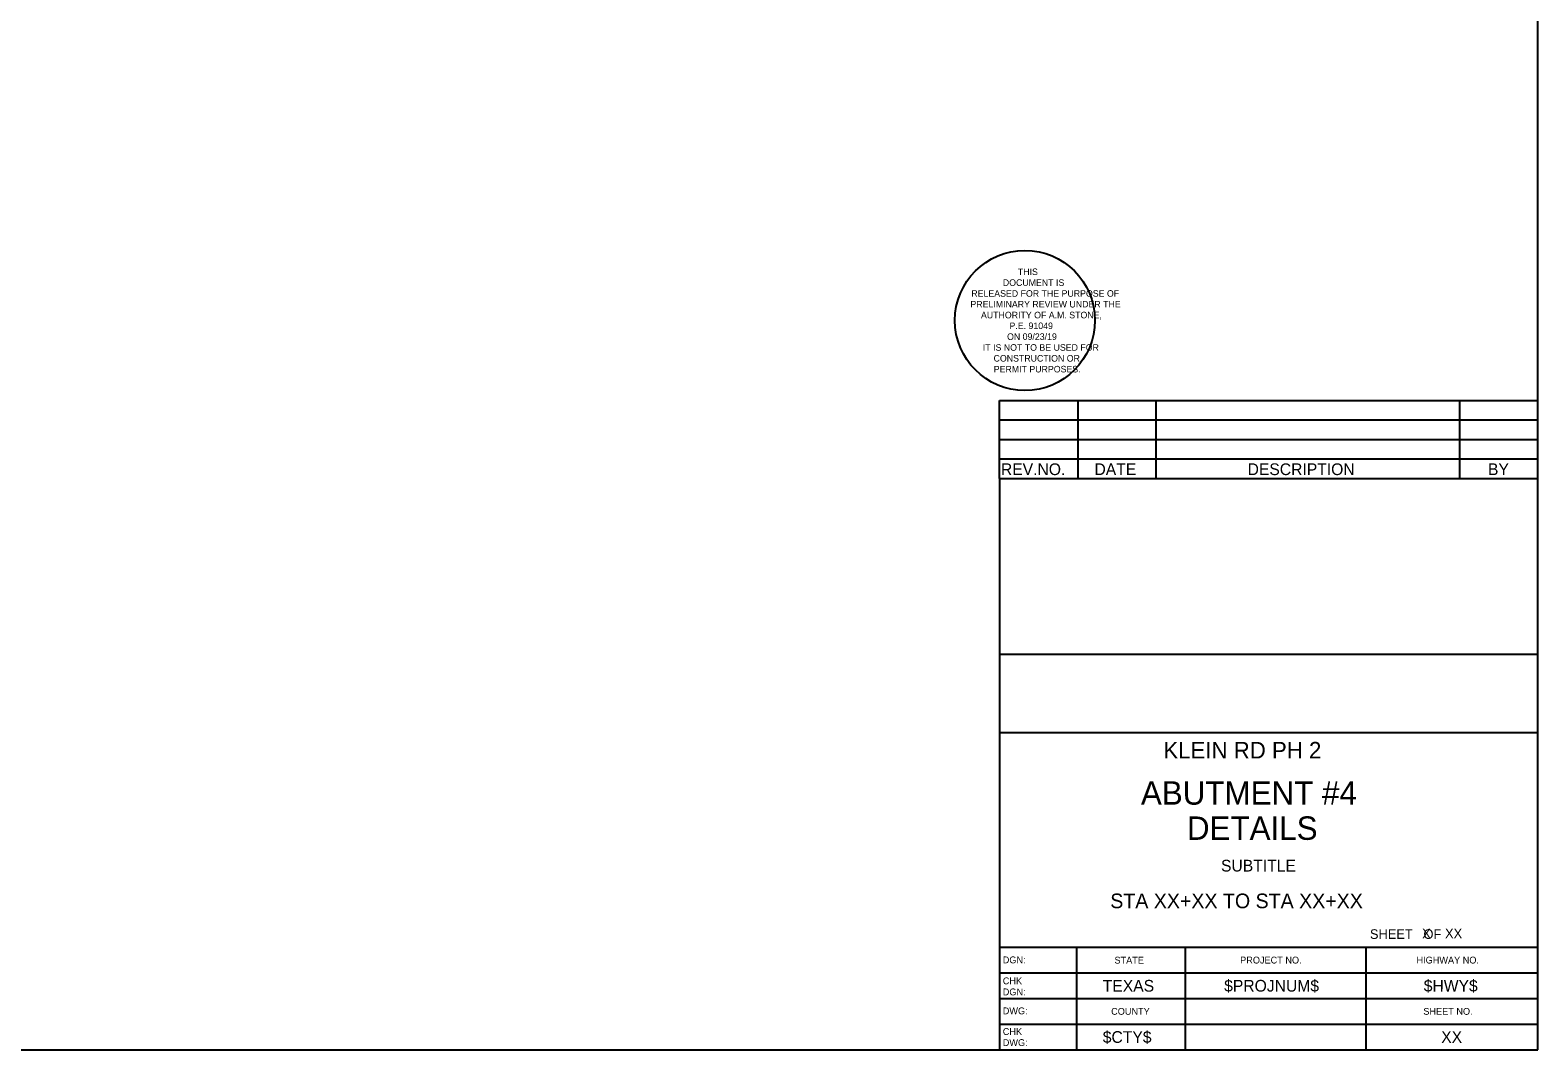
# Model space of a CAD drawing. Extents: x 926 to 1074, y 990 to 1081.
# Drawn here: x 1052.32 to 1067.76, y 1024.24 to 1034.69 of the extents above; entities that cross this region are included whole.
import ezdxf

# ---------------------------------------------------------------- set-up
doc = ezdxf.new("R2010")
doc.units = 0
for name, color, linetype in [('BORD_lines_major', 7, 'Continuous'), ('BORD_lines_minor', 7, 'Continuous'), ('BORD_text_large_1', 7, 'Continuous'), ('BORD_text_large_2', 7, 'Continuous'), ('BORD_text_SHEET', 7, 'Continuous'), ('BORD_text_small_1', 7, 'Continuous'), ('BORD_text_small_2', 7, 'Continuous'), ('BORD_text_small_3', 7, 'Continuous'), ('BORD_text_small_proj', 7, 'Continuous'), ('C-MS-ANNO-TTLB-STMP', 7, 'Continuous')]:
    doc.layers.add(name, color=color, linetype=linetype)

msp = doc.modelspace()

# ---------------------------------------------------------------- linework, layer by layer
at = {"layer": 'BORD_lines_major'}
for p, q in [((1067.759, 1024.245), (1067.759, 1045.127)), ((1036.673, 1024.245), (1067.759, 1024.245))]:
    msp.add_line(p, q, dxfattribs=at)
at = {"layer": 'BORD_lines_minor'}
for p, q in [((1062.248, 1030.895), (1067.759, 1030.895)), ((1062.248, 1030.095), (1062.248, 1030.895)), ((1063.048, 1030.895), (1063.048, 1030.095)), ((1063.848, 1030.895), (1063.848, 1030.095)), ((1066.959, 1030.095), (1066.959, 1030.895)), ((1062.248, 1030.695), (1067.759, 1030.695)), ((1062.248, 1030.495), (1067.759, 1030.495)), ((1062.248, 1030.295), (1067.759, 1030.295)), ((1062.248, 1030.095), (1067.759, 1030.095)), ((1062.248, 1030.095), (1062.248, 1028.295)), ((1062.248, 1028.295), (1067.759, 1028.295)), ((1062.248, 1028.295), (1062.248, 1024.245)), ((1062.248, 1027.495), (1067.759, 1027.495)), ((1062.248, 1025.295), (1067.759, 1025.295)), ((1063.035, 1025.295), (1063.035, 1024.245)), ((1064.148, 1025.295), (1064.148, 1024.245)), ((1065.998, 1025.295), (1065.998, 1024.245)), ((1062.248, 1025.032), (1067.759, 1025.032)), ((1062.248, 1024.77), (1067.759, 1024.77)), ((1062.248, 1024.507), (1067.759, 1024.507))]:
    msp.add_line(p, q, dxfattribs=at)
at = {"layer": 'C-MS-ANNO-TTLB-STMP'}
msp.add_circle((1062.507, 1031.713), 0.717, dxfattribs=at)

# ---------------------------------------------------------------- texts
at = {"layer": 'BORD_lines_minor'}
for s, p in [('REV.NO.', (1062.261, 1030.13)), ('DATE', (1063.219, 1030.13)), ('DESCRIPTION', (1064.787, 1030.13)), ('BY', (1067.249, 1030.13))]:
    msp.add_text(s, height=0.12, rotation=359.9834, dxfattribs=at).set_placement(p)
msp.add_text('KLEIN RD PH 2', height=0.17, dxfattribs=at).set_placement((1063.925, 1027.228))
at = {"layer": 'BORD_text_large_1'}
for s, p in [('ABUTMENT #4', (1063.695, 1026.755)), ('DETAILS', (1064.166, 1026.395))]:
    msp.add_text(s, height=0.24, dxfattribs=at).set_placement(p)
at = {"layer": 'BORD_text_large_2'}
msp.add_text('STA XX+XX TO STA XX+XX', height=0.15, dxfattribs=at).set_placement((1063.381, 1025.695))
at = {"layer": 'BORD_text_SHEET'}
msp.add_text('XX', height=0.12, dxfattribs=at).set_placement((1066.77, 1024.316))
at = {"layer": 'BORD_text_small_1'}
msp.add_text('SHEET   OF', height=0.0984, dxfattribs=at).set_placement((1066.04, 1025.381))
at = {"layer": 'BORD_text_small_2'}
msp.add_text('SUBTITLE', height=0.12, rotation=359.9834, dxfattribs=at).set_placement((1064.515, 1026.071))
at = {"layer": 'BORD_text_small_3'}
msp.add_text('X    XX', height=0.0984, dxfattribs=at).set_placement((1066.575, 1025.387))
at = {"layer": 'BORD_text_small_proj'}
for s, height, p in [('DGN:', 0.07, (1062.28, 1025.131)), ('STATE', 0.07, (1063.424, 1025.128)), ('PROJECT NO.', 0.07, (1064.711, 1025.129)), ('HIGHWAY NO.', 0.07, (1066.517, 1025.129)), ('CHK', 0.07, (1062.28, 1024.916)), ('DGN:', 0.07, (1062.28, 1024.803)), ('TEXAS', 0.12, (1063.304, 1024.841)), ('$HWY$', 0.12, (1066.591, 1024.841)), ('DWG:', 0.07, (1062.28, 1024.609)), ('COUNTY', 0.07, (1063.39, 1024.604)), ('SHEET NO.', 0.07, (1066.587, 1024.604)), ('CHK', 0.07, (1062.28, 1024.397)), ('$CTY$', 0.12, (1063.304, 1024.316)), ('DWG:', 0.07, (1062.28, 1024.284))]:
    msp.add_text(s, height=height, rotation=359.9834, dxfattribs=at).set_placement(p)
msp.add_text('$PROJNUM$', height=0.12, dxfattribs=at).set_placement((1064.547, 1024.841))
at = {"layer": 'C-MS-ANNO-TTLB-STMP'}
for s, height, p in [('DOCUMENT IS', 0.06723, (1062.281, 1032.067)), ('THIS', 0.0672, (1062.435, 1032.178)), ('RELEASED FOR THE PURPOSE OF', 0.06723, (1061.958, 1031.956)), ('PRELIMINARY REVIEW UNDER THE', 0.06723, (1061.949, 1031.846)), ('AUTHORITY OF A.M. STONE,', 0.06723, (1062.057, 1031.735)), ('P.E. 91049', 0.0672, (1062.349, 1031.625)), ('ON 09/23/19', 0.06723, (1062.324, 1031.514)), ('IT IS NOT TO BE USED FOR', 0.06723, (1062.076, 1031.403)), ('CONSTRUCTION OR', 0.06723, (1062.186, 1031.292)), ('PERMIT PURPOSES.', 0.06723, (1062.188, 1031.181))]:
    msp.add_text(s, height=height, rotation=360, dxfattribs=at).set_placement(p)

doc.saveas('drawing.dxf')
